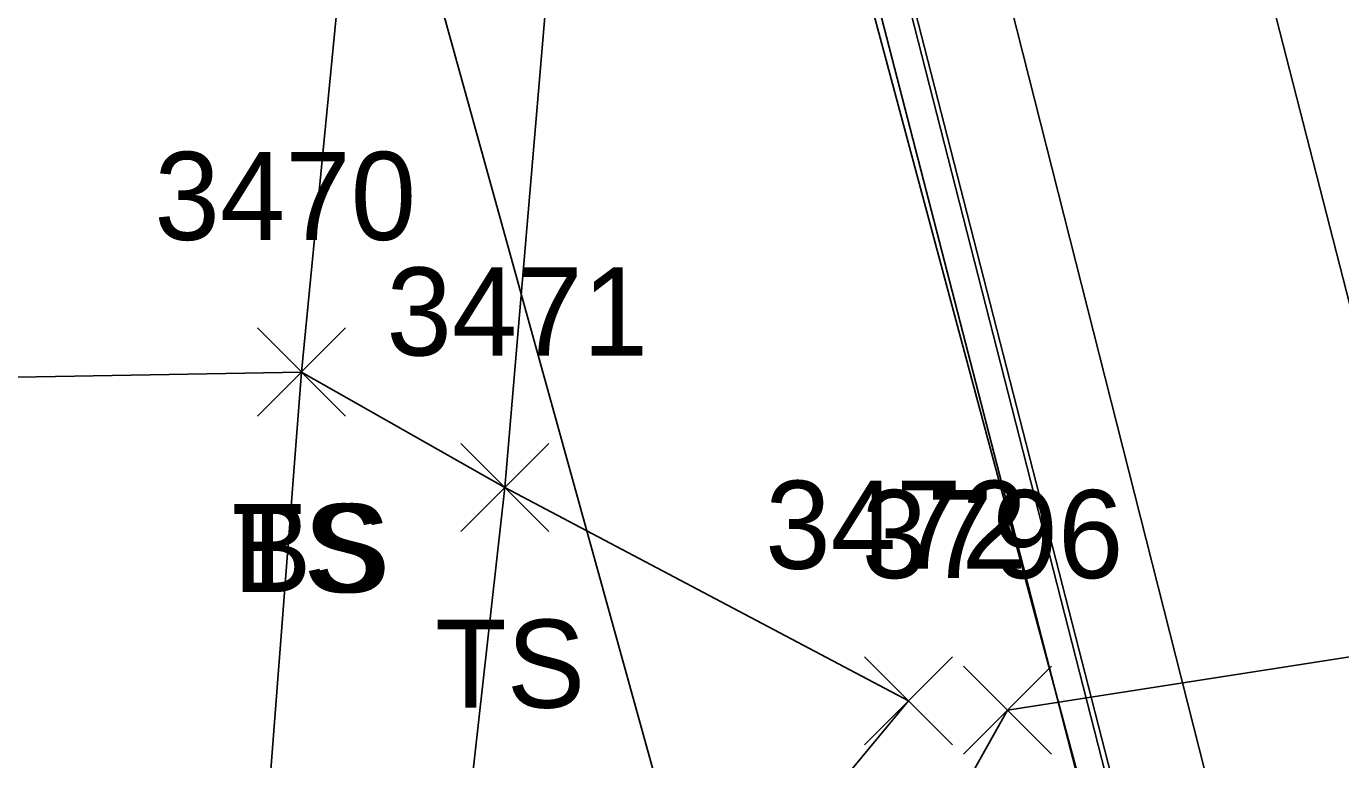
# Model space of a CAD drawing. Extents: x 1601151 to 1602912, y 499508 to 501770.
# Drawn here: x 1601576.97 to 1601606.85, y 500563.94 to 500580.6 of the extents above; entities that cross this region are included whole.
import ezdxf

# ---------------------------------------------------------------- set-up
doc = ezdxf.new("R2010")
doc.units = 0
for name, color, linetype in [('BB', 7, 'Continuous'), ('BDC', 7, 'Continuous'), ('BF', 7, 'Continuous'), ('BR', 7, 'Continuous'), ('L_A', 7, 'Continuous'), ('L_I', 7, 'Continuous'), ('L_TIC', 7, 'Continuous'), ('LELB', 7, 'Continuous'), ('UCO', 7, 'Continuous')]:
    doc.layers.add(name, color=color, linetype=linetype)

msp = doc.modelspace()

# ---------------------------------------------------------------- linework, layer by layer
at = {"layer": 'BB'}
for points in [[(1601610.48, 500560.951), (1601601.066, 500597.638)], [(1601604.841, 500559.444), (1601595.48, 500596.326)]]:
    msp.add_lwpolyline(points, dxfattribs=at)
at = {"layer": 'BDC'}
for points in [[(1601521.711, 500869.959), (1601522.401, 500870.191), (1601530.668, 500838.288), (1601539.742, 500803.087), (1601549.8, 500763.941), (1601562.902, 500713.198), (1601575.298, 500665.088), (1601584.682, 500628.799), (1601595.241, 500588.098), (1601603.293, 500556.622), (1601602.827, 500556.326)], [(1601522.54, 500870.251), (1601530.887, 500838.161), (1601539.773, 500803.176), (1601550.059, 500763.65), (1601563.09, 500713.388), (1601575.504, 500665.097), (1601584.832, 500628.831), (1601595.285, 500588.334), (1601603.432, 500556.591), (1601602.763, 500556.075)]]:
    msp.add_lwpolyline(points, dxfattribs=at)
at = {"layer": 'BF'}
msp.add_lwpolyline([(1601521.711, 500869.959), (1601529.926, 500837.537), (1601538.825, 500802.891), (1601549.015, 500763.542), (1601561.986, 500712.939), (1601574.422, 500664.924), (1601583.827, 500628.557), (1601594.342, 500587.938), (1601602.827, 500556.326)], dxfattribs=at)
at = {"layer": 'BR'}
msp.add_lwpolyline([(1601521.915, 500869.371), (1601530.025, 500838.058), (1601539.084, 500802.864), (1601549.326, 500763.869), (1601562.422, 500713.041), (1601574.564, 500665.146), (1601584.098, 500628.637), (1601594.598, 500587.839), (1601602.424, 500557.542)], dxfattribs=at)
at = {"layer": 'L_TIC'}
for points in [[(1601582.232, 500571.746), (1601584.232, 500573.746)], [(1601584.232, 500571.746), (1601582.232, 500573.746)], [(1601582.232, 500571.746), (1601584.232, 500573.746)], [(1601584.232, 500571.746), (1601582.232, 500573.746)], [(1601586.852, 500569.121), (1601588.852, 500571.121)], [(1601588.852, 500569.121), (1601586.852, 500571.121)], [(1601586.852, 500569.121), (1601588.852, 500571.121)], [(1601588.852, 500569.121), (1601586.852, 500571.121)], [(1601596.031, 500564.276), (1601598.031, 500566.276)], [(1601598.031, 500564.276), (1601596.031, 500566.276)], [(1601598.278, 500564.065), (1601600.278, 500566.065)], [(1601600.278, 500564.065), (1601598.278, 500566.065)]]:
    msp.add_lwpolyline(points, dxfattribs=at)
at = {"layer": 'LELB'}
for points in [[(1601587.012, 500620.349), (1601586.664, 500611.463), (1601589.525, 500603.909), (1601584.892, 500589.745), (1601583.232, 500572.746), (1601582.008, 500556.938), (1601586.093, 500551.377), (1601586.32, 500550.708)], [(1601595.511, 500601.966), (1601589.477, 500589.294), (1601587.852, 500570.121), (1601586.567, 500558.707), (1601586.093, 500551.377)], [(1601391.392, 500554.189), (1601389.462, 500565.783), (1601399.295, 500566.987), (1601429.3, 500567.089), (1601474.92, 500572.476), (1601521.564, 500573.328), (1601560.201, 500571.77), (1601571.602, 500572.536), (1601583.232, 500572.746), (1601587.852, 500570.121), (1601597.031, 500565.276), (1601591.651, 500558.786)], [(1601599.278, 500565.065), (1601626.373, 500569.282)], [(1601590.204, 500521.239), (1601598.352, 500527.885), (1601592.341, 500548.06), (1601594.686, 500556.882), (1601599.278, 500565.065)]]:
    msp.add_lwpolyline(points, dxfattribs=at)
at = {"layer": 'UCO'}
msp.add_lwpolyline([(1601595.966, 500546.616), (1601489.931, 500928.889)], dxfattribs=at)

# ---------------------------------------------------------------- texts
at = {"layer": 'L_A'}
for s, p in [('TS', (1601581.641, 500567.746)), ('BS', (1601581.673, 500567.746)), ('TS', (1601586.261, 500565.121)), ('TS', (1601586.261, 500565.121))]:
    msp.add_text(s, height=2, dxfattribs=at).set_placement(p)
at = {"layer": 'L_I'}
for s, p in [('3470', (1601579.885, 500575.746)), ('3470', (1601579.885, 500575.746)), ('3471', (1601585.159, 500573.121)), ('3471', (1601585.159, 500573.121)), ('3472', (1601593.771, 500568.276)), ('3796', (1601595.963, 500568.065))]:
    msp.add_text(s, height=2, dxfattribs=at).set_placement(p)

doc.saveas('drawing.dxf')
